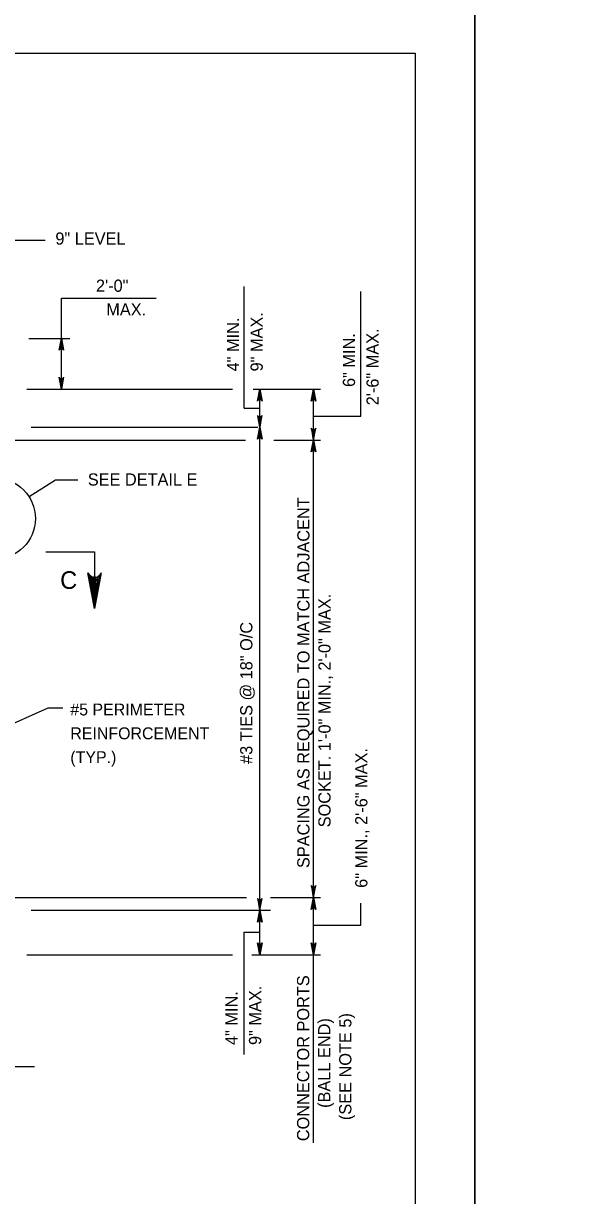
# Model space of a CAD drawing. Extents: x 3385 to 6532, y -616 to 1166.
# Drawn here: x 5329.7 to 5470.5, y 269.1 to 564.2 of the extents above; entities that cross this region are included whole.
import ezdxf

# ---------------------------------------------------------------- set-up
doc = ezdxf.new("R2010")
doc.units = 0
for name, color, linetype in [('1', 7, 'Continuous'), ('2', 7, 'Continuous'), ('PLT-BNDY', 7, 'Continuous')]:
    doc.layers.add(name, color=color, linetype=linetype)

msp = doc.modelspace()

# ---------------------------------------------------------------- linework, layer by layer
at = {"layer": '1'}
for p, q in [((5309.6, 509.66), (5335.1, 509.66)), ((5385.2, 467.33), (5385.2, 497.92)), ((5414.65, 465.28), (5414.65, 496.7)), ((5339.22, 472.1), (5339.22, 495.04)), ((5339.22, 495.04), (5363.1, 495.04)), ((5331.05, 484.9), (5341.3, 484.9)), ((5330.5, 472.1), (5382.26, 472.1)), ((5387.48, 472.1), (5404.49, 472.1)), ((5389.17, 329.7), (5389.17, 472.1)), ((5402.7, 282.35), (5402.7, 472.1)), ((5385.2, 467.33), (5389.17, 467.33)), ((5402.7, 465.28), (5414.65, 465.28)), ((5331.56, 462.5), (5388.68, 462.5)), ((5325.16, 459.3), (5385.56, 459.3)), ((5392.69, 459.3), (5404.49, 459.3)), ((5337.72, 449.16), (5331.08, 444.98)), ((5343.32, 449.16), (5337.72, 449.16)), ((5335.31, 431.16), (5347.58, 431.16)), ((5347.58, 431.16), (5347.58, 416.9)), ((5335.79, 391.81), (5323.74, 386.42)), ((5339.56, 391.81), (5335.79, 391.81)), ((5327.41, 344.1), (5385.83, 344.1)), ((5391.86, 344.1), (5404.49, 344.1)), ((5414.65, 337.16), (5414.65, 342.72)), ((5331.56, 340.9), (5391.86, 340.9)), ((5402.7, 337.16), (5414.65, 337.16)), ((5385.2, 304.54), (5385.2, 335.4)), ((5385.2, 335.4), (5389.17, 335.4)), ((5330.5, 329.7), (5382.26, 329.7)), ((5387.2, 329.7), (5404.49, 329.7)), ((5177.83, 301.58), (5332.44, 301.58))]:
    msp.add_line(p, q, dxfattribs=at)
for points in [[(5339.22, 484.9), (5339.78, 481.92), (5339.7, 482.03), (5339.62, 482.15), (5339.52, 482.21), (5339.42, 482.27), (5339.32, 482.29), (5339.22, 482.3), (5339.12, 482.29), (5339.02, 482.27), (5338.92, 482.21), (5338.82, 482.15), (5338.74, 482.03), (5338.66, 481.92), (5339.22, 484.9), (5338.74, 482.03), (5338.82, 482.15), (5339.22, 484.9), (5338.92, 482.21), (5339.02, 482.27), (5339.22, 484.9), (5339.12, 482.29), (5339.22, 482.3), (5339.22, 484.9), (5339.32, 482.29), (5339.42, 482.27), (5339.22, 484.9), (5339.52, 482.21), (5339.62, 482.15), (5339.22, 484.9), (5339.7, 482.03)], [(5339.22, 472.1), (5338.66, 475.09), (5338.74, 474.97), (5338.82, 474.86), (5338.92, 474.8), (5339.02, 474.74), (5339.12, 474.72), (5339.22, 474.7), (5339.32, 474.72), (5339.42, 474.74), (5339.52, 474.8), (5339.62, 474.86), (5339.7, 474.97), (5339.78, 475.09), (5339.22, 472.1), (5339.7, 474.97), (5339.62, 474.86), (5339.22, 472.1), (5339.52, 474.8), (5339.42, 474.74), (5339.22, 472.1), (5339.32, 474.72), (5339.22, 474.7), (5339.22, 472.1), (5339.12, 474.72), (5339.02, 474.74), (5339.22, 472.1), (5338.92, 474.8), (5338.82, 474.86), (5339.22, 472.1), (5338.74, 474.97)], [(5389.17, 472.1), (5389.73, 469.12), (5389.65, 469.23), (5389.57, 469.35), (5389.47, 469.41), (5389.37, 469.47), (5389.27, 469.49), (5389.17, 469.5), (5389.07, 469.49), (5388.97, 469.47), (5388.87, 469.41), (5388.77, 469.35), (5388.69, 469.23), (5388.61, 469.12), (5389.17, 472.1), (5388.69, 469.23), (5388.77, 469.35), (5389.17, 472.1), (5388.87, 469.41), (5388.97, 469.47), (5389.17, 472.1), (5389.07, 469.49), (5389.17, 469.5), (5389.17, 472.1), (5389.27, 469.49), (5389.37, 469.47), (5389.17, 472.1), (5389.47, 469.41), (5389.57, 469.35), (5389.17, 472.1), (5389.65, 469.23)], [(5402.7, 472.1), (5403.26, 469.12), (5403.1, 469.35), (5402.9, 469.47), (5402.7, 469.5), (5402.5, 469.47), (5402.3, 469.35), (5402.14, 469.12), (5402.7, 472.1), (5402.3, 469.35), (5402.5, 469.47), (5402.7, 472.1), (5402.7, 469.5), (5402.9, 469.47), (5402.7, 472.1), (5403.1, 469.35)], [(5389.17, 462.5), (5389.73, 465.49), (5389.65, 465.37), (5389.57, 465.26), (5389.47, 465.2), (5389.37, 465.14), (5389.27, 465.12), (5389.17, 465.1), (5389.07, 465.12), (5388.97, 465.14), (5388.87, 465.2), (5388.77, 465.26), (5388.69, 465.37), (5388.61, 465.49), (5389.17, 462.5), (5388.69, 465.37), (5388.77, 465.26), (5389.17, 462.5), (5388.87, 465.2), (5388.97, 465.14), (5389.17, 462.5), (5389.07, 465.12), (5389.17, 465.1), (5389.17, 462.5), (5389.27, 465.12), (5389.37, 465.14), (5389.17, 462.5), (5389.47, 465.2), (5389.57, 465.26), (5389.17, 462.5), (5389.65, 465.37)], [(5389.17, 462.5), (5389.73, 459.52), (5389.65, 459.63), (5389.57, 459.75), (5389.47, 459.81), (5389.37, 459.87), (5389.27, 459.89), (5389.17, 459.9), (5389.07, 459.89), (5388.97, 459.87), (5388.87, 459.81), (5388.77, 459.75), (5388.69, 459.63), (5388.61, 459.52), (5389.17, 462.5), (5388.69, 459.63), (5388.77, 459.75), (5389.17, 462.5), (5388.87, 459.81), (5388.97, 459.87), (5389.17, 462.5), (5389.07, 459.89), (5389.17, 459.9), (5389.17, 462.5), (5389.27, 459.89), (5389.37, 459.87), (5389.17, 462.5), (5389.47, 459.81), (5389.57, 459.75), (5389.17, 462.5), (5389.65, 459.63)], [(5402.7, 459.3), (5403.26, 462.29), (5403.1, 462.06), (5402.9, 461.94), (5402.7, 461.9), (5402.5, 461.94), (5402.3, 462.06), (5402.14, 462.29), (5402.7, 459.3), (5402.3, 462.06), (5402.5, 461.94), (5402.7, 459.3), (5402.7, 461.9), (5402.9, 461.94), (5402.7, 459.3), (5403.1, 462.06)], [(5402.7, 459.3), (5403.26, 456.32), (5403.1, 456.55), (5402.9, 456.67), (5402.7, 456.7), (5402.5, 456.67), (5402.3, 456.55), (5402.14, 456.32), (5402.7, 459.3), (5402.3, 456.55), (5402.5, 456.67), (5402.7, 459.3), (5402.7, 456.7), (5402.9, 456.67), (5402.7, 459.3), (5403.1, 456.55)], [(5347.58, 416.9), (5345.9, 425.84), (5346.14, 425.5), (5346.38, 425.16), (5346.68, 424.98), (5346.98, 424.8), (5347.28, 424.75), (5347.58, 424.7), (5347.88, 424.75), (5348.18, 424.8), (5348.48, 424.98), (5348.78, 425.16), (5349.02, 425.5), (5349.26, 425.84), (5347.58, 416.9), (5349.02, 425.5), (5348.78, 425.16), (5347.58, 416.9), (5348.48, 424.98), (5348.18, 424.8), (5347.58, 416.9), (5347.88, 424.75), (5347.58, 424.7), (5347.58, 416.9), (5347.28, 424.75), (5346.98, 424.8), (5347.58, 416.9), (5346.68, 424.98), (5346.38, 425.16), (5347.58, 416.9), (5346.14, 425.5)], [(5402.7, 344.1), (5403.26, 347.09), (5403.1, 346.86), (5402.9, 346.74), (5402.7, 346.7), (5402.5, 346.74), (5402.3, 346.86), (5402.14, 347.09), (5402.7, 344.1), (5402.3, 346.86), (5402.5, 346.74), (5402.7, 344.1), (5402.7, 346.7), (5402.9, 346.74), (5402.7, 344.1), (5403.1, 346.86)], [(5389.17, 340.9), (5389.73, 343.89), (5389.57, 343.66), (5389.37, 343.54), (5389.17, 343.5), (5388.97, 343.54), (5388.77, 343.66), (5388.61, 343.89), (5389.17, 340.9), (5388.77, 343.66), (5388.97, 343.54), (5389.17, 340.9), (5389.17, 343.5), (5389.37, 343.54), (5389.17, 340.9), (5389.57, 343.66)], [(5402.7, 344.1), (5403.26, 341.12), (5403.1, 341.35), (5402.9, 341.47), (5402.7, 341.5), (5402.5, 341.47), (5402.3, 341.35), (5402.14, 341.12), (5402.7, 344.1), (5402.3, 341.35), (5402.5, 341.47), (5402.7, 344.1), (5402.7, 341.5), (5402.9, 341.47), (5402.7, 344.1), (5403.1, 341.35)], [(5389.17, 340.9), (5389.73, 337.92), (5389.57, 338.15), (5389.37, 338.27), (5389.17, 338.3), (5388.97, 338.27), (5388.77, 338.15), (5388.61, 337.92), (5389.17, 340.9), (5388.77, 338.15), (5388.97, 338.27), (5389.17, 340.9), (5389.17, 338.3), (5389.37, 338.27), (5389.17, 340.9), (5389.57, 338.15)], [(5389.17, 329.7), (5388.61, 332.69), (5388.77, 332.46), (5388.97, 332.34), (5389.17, 332.3), (5389.37, 332.34), (5389.57, 332.46), (5389.73, 332.69), (5389.17, 329.7), (5389.57, 332.46), (5389.37, 332.34), (5389.17, 329.7), (5389.17, 332.3), (5388.97, 332.34), (5389.17, 329.7), (5388.77, 332.46)], [(5402.7, 329.7), (5402.14, 332.69), (5402.3, 332.46), (5402.5, 332.34), (5402.7, 332.3), (5402.9, 332.34), (5403.1, 332.46), (5403.26, 332.69), (5402.7, 329.7), (5403.1, 332.46), (5402.9, 332.34), (5402.7, 329.7), (5402.7, 332.3), (5402.5, 332.34), (5402.7, 329.7), (5402.3, 332.46)]]:
    msp.add_lwpolyline(points, dxfattribs=at)
msp.add_circle((5322.42, 439.53), 10.24, dxfattribs=at)
at = {"layer": '2'}
for p, q in [((4642.34, 556.69), (5428.34, 556.69)), ((5428.34, 556.69), (5428.34, -7.31))]:
    msp.add_line(p, q, dxfattribs=at)
at = {"layer": 'PLT-BNDY'}
for points in [[(4602.34, 571.69), (5443.34, 571.69), (5443.34, -22.31), (4602.34, -22.31)], [(5443.34, 571.69), (6284.34, 571.69), (6284.34, -22.31), (5443.34, -22.31)]]:
    msp.add_lwpolyline(points, close=True, dxfattribs=at)

# ---------------------------------------------------------------- texts
at = {"layer": '1'}
for s, height, p in [('9" LEVEL', 3.072, (5337.69, 508.49)), ('2\'-0"', 3.072, (5347.91, 496.62)), ('MAX.', 3.072, (5350.51, 490.66)), ('SEE DETAIL E', 3.072, (5345.85, 447.83)), ('C', 4.45, (5338.9, 421.81)), ('#5 PERIMETER', 3, (5341.46, 389.95)), ('REINFORCEMENT', 3, (5341.46, 383.95)), ('(TYP.)', 3, (5341.46, 377.95))]:
    msp.add_text(s, height=height, dxfattribs=at).set_placement(p)
for s, p in [('9" MAX.', (5389.92, 476.57)), ('4" MIN.', (5383.97, 476.57)), ('2\'-6" MAX.', (5419.11, 468.04)), ('6" MIN.', (5413.16, 472.65)), ('SPACING AS REQUIRED TO MATCH ADJACENT', (5401.69, 351.52)), ('SOCKET. 1\'-0" MIN., 2\'-0" MAX.', (5407, 361.78)), ('#3 TIES @ 18" O/C', (5387.31, 377.74)), ('6" MIN., 2\'-6" MAX.', (5416.27, 346.54)), ('CONNECTOR PORTS', (5401.62, 282.75)), ('4" MIN.', (5383.57, 306.97)), ('9" MAX.', (5389.52, 306.97)), ('(BALL END)', (5406.93, 291.13)), ('(SEE NOTE 5)', (5412.24, 288.06))]:
    msp.add_text(s, height=3.072, rotation=90, dxfattribs=at).set_placement(p)

doc.saveas('drawing.dxf')
